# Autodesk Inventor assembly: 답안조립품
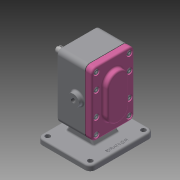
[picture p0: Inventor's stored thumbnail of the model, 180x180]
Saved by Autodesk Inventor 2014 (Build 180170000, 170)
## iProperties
Created: 2020-04
Part Number: 답안조립품
Document SubType Name: Assembly
Designer: kh
Author: kh
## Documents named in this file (11)
- C:\Users\kh\Desktop\700407V1013\답안조립품.iam
- C:\Users\kh\Desktop\700407V1013\본체.ipt
- C:\Users\kh\Desktop\700407V1013\개스킷.ipt
- C:\Users\kh\Desktop\700407V1013\메인축.ipt
- C:\Users\kh\Desktop\700407V1013\베어링부시.ipt
- C:\Users\kh\Desktop\700407V1013\볼트 M5.ipt
- C:\Users\kh\Desktop\700407V1013\서브축.ipt
- C:\Users\kh\Desktop\700407V1013\스퍼기어.ipt
- C:\Users\kh\Desktop\700407V1013\오일 실 16 28 7.ipt
- C:\Users\kh\Desktop\700407V1013\커버.ipt
- C:\Users\kh\Desktop\700407V1013\키 6 x 6 x 18.ipt
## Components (1 placed, 1 different names)
1. 개스킷:1 — 플러쉬:1, 플러쉬:2
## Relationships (2: Flush 2)
- 플러쉬:1 [Flush]: 개스킷:1
- 플러쉬:2 [Flush]: 개스킷:1
